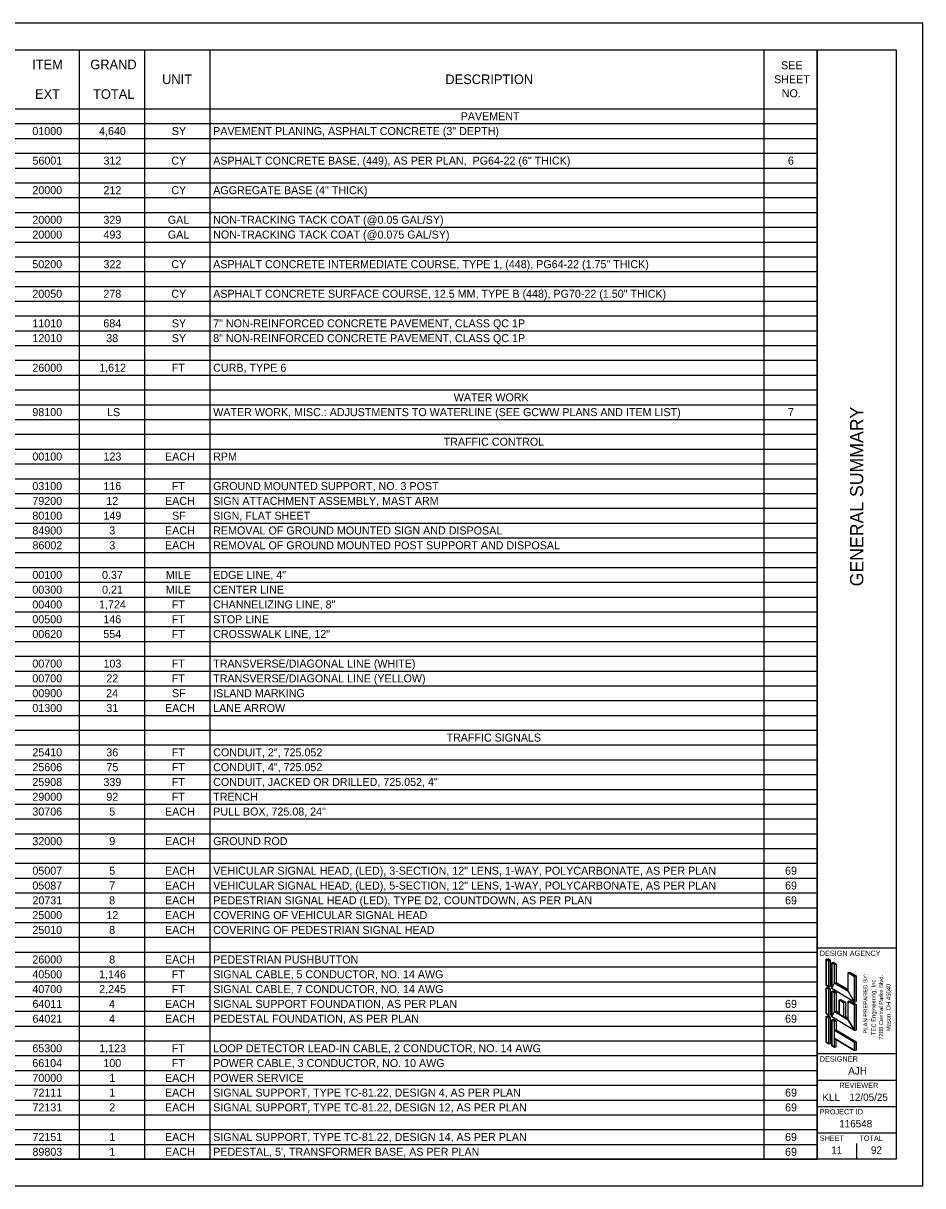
# Model space of a CAD drawing. Extents: x 0 to 34, y 0 to 22.
# Drawn here: x 16.98 to 34, y 0 to 22 of the extents above; entities that cross this region are included whole.
import ezdxf

# ---------------------------------------------------------------- set-up
doc = ezdxf.new("R2010")
doc.units = 0
for name, color, linetype in [('Default', 7, 'Continuous'), ('SH_Border', 7, 'Continuous'), ('SH_Cut_Line', 7, 'Continuous'), ('SH_Data', 7, 'Continuous'), ('SH_Text', 7, 'Continuous')]:
    doc.layers.add(name, color=color, linetype=linetype)

msp = doc.modelspace()

# ---------------------------------------------------------------- linework, layer by layer
at = {"layer": 'SH_Border'}
for p, q in [((32, 0.5), (32, 21.5)), ((32, 4.5), (33.5, 4.5)), ((32, 2.5), (33.5, 2.5)), ((32, 2), (33.5, 2)), ((32, 1.5), (33.5, 1.5)), ((32, 1), (33.5, 1))]:
    msp.add_line(p, q, dxfattribs=at)
msp.add_lwpolyline([(1.5, 21.5), (33.5, 21.5), (33.5, 0.5), (1.5, 0.5)], close=True, dxfattribs=at)
at = {"layer": 'SH_Cut_Line'}
msp.add_lwpolyline([(0, 0), (34, 0), (34, 22), (0, 22)], close=True, dxfattribs=at)
at = {"layer": 'SH_Data'}
for p, q in [((32.75, 3.5), (32.75, 3.5)), ((32.375, 0.675), (32.375, 0.675)), ((32.75, 0.5), (32.75, 0.8))]:
    msp.add_line(p, q, dxfattribs=at)
at = {"layer": 'SH_Text'}
for p, q in [((1.5, 21.5), (32, 21.5)), ((18.035, 21.5), (18.035, 0.502)), ((19.27, 21.5), (19.27, 0.502)), ((20.505, 21.5), (20.505, 0.502)), ((30.995, 21.5), (30.995, 0.502)), ((32, 21.5), (32, 0.502)), ((1.5, 20.38), (32, 20.38)), ((1.5, 20.1), (32, 20.1)), ((1.5, 19.82), (32, 19.82)), ((1.5, 19.54), (32, 19.54)), ((1.5, 19.26), (32, 19.26)), ((1.5, 18.98), (32, 18.98)), ((1.5, 18.7), (32, 18.7)), ((1.5, 18.42), (32, 18.42)), ((1.5, 18.14), (32, 18.14)), ((1.5, 17.86), (32, 17.86)), ((1.5, 17.58), (32, 17.58)), ((1.5, 17.3), (32, 17.3)), ((1.5, 17.021), (32, 17.021)), ((1.5, 16.741), (32, 16.741)), ((1.5, 16.461), (32, 16.461)), ((1.5, 16.181), (32, 16.181)), ((1.5, 15.901), (32, 15.901)), ((1.5, 15.621), (32, 15.621)), ((1.5, 15.341), (32, 15.341)), ((1.5, 15.061), (32, 15.061)), ((1.5, 14.781), (32, 14.781)), ((1.5, 14.501), (32, 14.501)), ((1.5, 14.221), (32, 14.221)), ((1.5, 13.941), (32, 13.941)), ((1.5, 13.661), (32, 13.661)), ((1.5, 13.381), (32, 13.381)), ((1.5, 13.101), (32, 13.101)), ((1.5, 12.821), (32, 12.821)), ((1.5, 12.541), (32, 12.541)), ((1.5, 12.261), (32, 12.261)), ((1.5, 11.981), (32, 11.981)), ((1.5, 11.701), (32, 11.701)), ((1.5, 11.421), (32, 11.421)), ((1.5, 11.141), (32, 11.141)), ((1.5, 10.861), (32, 10.861)), ((1.5, 10.581), (32, 10.581)), ((1.5, 10.301), (32, 10.301)), ((1.5, 10.021), (32, 10.021)), ((1.5, 9.741), (32, 9.741)), ((1.5, 9.461), (32, 9.461)), ((1.5, 9.181), (32, 9.181)), ((1.5, 8.901), (32, 8.901)), ((1.5, 8.621), (32, 8.621)), ((1.5, 8.342), (32, 8.342)), ((1.5, 8.062), (32, 8.062)), ((1.5, 7.782), (32, 7.782)), ((1.5, 7.502), (32, 7.502)), ((1.5, 7.222), (32, 7.222)), ((1.5, 6.942), (32, 6.942)), ((1.5, 6.662), (32, 6.662)), ((1.5, 6.382), (32, 6.382)), ((1.5, 6.102), (32, 6.102)), ((1.5, 5.822), (32, 5.822)), ((1.5, 5.542), (32, 5.542)), ((1.5, 5.262), (32, 5.262)), ((1.5, 4.982), (32, 4.982)), ((1.5, 4.702), (32, 4.702)), ((1.5, 4.422), (32, 4.422)), ((32.169, 4.285), (32.201, 4.294)), ((32.169, 3.799), (32.169, 4.285)), ((32.223, 4.253), (32.169, 4.285)), ((32.255, 4.261), (32.201, 4.294)), ((32.223, 4.253), (32.255, 4.261)), ((32.223, 3.767), (32.223, 4.253)), ((32.255, 3.775), (32.255, 4.261)), ((32.277, 4.221), (32.309, 4.229)), ((32.331, 4.188), (32.277, 4.221)), ((32.277, 3.735), (32.277, 4.221)), ((32.309, 4.229), (32.363, 4.196)), ((32.331, 4.188), (32.363, 4.196)), ((32.331, 3.837), (32.331, 4.188)), ((32.363, 4.196), (32.363, 3.845)), ((1.5, 4.142), (32, 4.142)), ((32.587, 4.034), (32.62, 4.042)), ((32.587, 3.683), (32.587, 4.034)), ((32.709, 3.961), (32.587, 4.034)), ((32.62, 4.042), (32.741, 3.97)), ((32.709, 3.961), (32.741, 3.97)), ((32.709, 3.475), (32.709, 3.961)), ((32.741, 3.97), (32.741, 3.484)), ((1.5, 3.862), (32, 3.862)), ((32.223, 3.767), (32.169, 3.799)), ((32.169, 3.745), (32.201, 3.754)), ((32.169, 3.259), (32.169, 3.745)), ((32.223, 3.713), (32.169, 3.745)), ((32.255, 3.722), (32.201, 3.754)), ((32.223, 3.767), (32.255, 3.775)), ((32.331, 3.837), (32.363, 3.845)), ((32.587, 3.683), (32.331, 3.837)), ((32.363, 3.845), (32.587, 3.711)), ((1.5, 3.582), (32, 3.582)), ((32.223, 3.713), (32.255, 3.722)), ((32.223, 3.227), (32.223, 3.713)), ((32.255, 3.236), (32.255, 3.722)), ((32.709, 3.475), (32.277, 3.735)), ((32.277, 3.681), (32.309, 3.689)), ((32.277, 3.195), (32.277, 3.681)), ((32.331, 3.648), (32.277, 3.681)), ((32.309, 3.689), (32.363, 3.656)), ((32.331, 3.648), (32.363, 3.656)), ((32.331, 3.297), (32.331, 3.648)), ((32.363, 3.656), (32.363, 3.305)), ((32.415, 3.519), (32.448, 3.527)), ((32.448, 3.527), (32.535, 3.474)), ((1.5, 3.302), (32, 3.302)), ((32.331, 3.297), (32.363, 3.305)), ((32.363, 3.305), (32.415, 3.274)), ((32.415, 3.519), (32.415, 3.247)), ((32.415, 3.519), (32.503, 3.466)), ((32.503, 3.466), (32.535, 3.474)), ((32.503, 3.466), (32.503, 3.194)), ((32.535, 3.474), (32.535, 3.202)), ((32.587, 3.494), (32.62, 3.502)), ((32.587, 3.143), (32.587, 3.494)), ((32.709, 3.421), (32.587, 3.494)), ((32.62, 3.502), (32.741, 3.43)), ((32.709, 3.475), (32.741, 3.484)), ((32.709, 3.421), (32.741, 3.43)), ((32.709, 2.935), (32.709, 3.421)), ((32.741, 3.43), (32.741, 2.944)), ((32.223, 3.227), (32.169, 3.259)), ((32.169, 3.205), (32.201, 3.215)), ((32.169, 2.719), (32.169, 3.205)), ((32.223, 3.173), (32.169, 3.205)), ((32.255, 3.181), (32.201, 3.215)), ((32.222, 3.173), (32.255, 3.181)), ((32.223, 3.227), (32.255, 3.236)), ((32.223, 2.687), (32.223, 3.173)), ((32.255, 2.695), (32.255, 3.181)), ((32.709, 2.935), (32.277, 3.195)), ((32.277, 3.141), (32.309, 3.151)), ((32.331, 3.108), (32.277, 3.141)), ((32.277, 2.655), (32.277, 3.141)), ((32.309, 3.151), (32.363, 3.116)), ((32.415, 3.247), (32.331, 3.297)), ((32.331, 3.108), (32.363, 3.116)), ((32.331, 2.944), (32.331, 3.108)), ((32.363, 3.116), (32.363, 2.952)), ((32.503, 3.194), (32.535, 3.202)), ((32.587, 3.143), (32.503, 3.194)), ((32.535, 3.202), (32.587, 3.171)), ((1.5, 3.022), (32, 3.022)), ((32.331, 2.944), (32.363, 2.952)), ((32.331, 2.944), (32.709, 2.717)), ((32.363, 2.952), (32.741, 2.725)), ((32.709, 2.935), (32.741, 2.944)), ((1.5, 2.742), (32, 2.742)), ((32.223, 2.687), (32.169, 2.719)), ((32.223, 2.687), (32.255, 2.695)), ((32.331, 2.622), (32.277, 2.655)), ((32.331, 2.787), (32.709, 2.56)), ((32.331, 2.622), (32.331, 2.787)), ((32.363, 2.63), (32.363, 2.767)), ((32.709, 2.717), (32.741, 2.725)), ((32.709, 2.56), (32.709, 2.717)), ((32.741, 2.725), (32.741, 2.568)), ((1.5, 2.462), (32, 2.462)), ((32.331, 2.622), (32.363, 2.63)), ((32.709, 2.56), (32.741, 2.568)), ((1.5, 2.182), (32, 2.182)), ((1.5, 1.902), (32, 1.902)), ((1.5, 1.622), (32, 1.622)), ((1.5, 1.342), (32, 1.342)), ((1.5, 1.062), (32, 1.062)), ((1.5, 0.782), (32, 0.782)), ((1.5, 0.502), (32, 0.502))]:
    msp.add_line(p, q, dxfattribs=at)
for points in [[(32.169, 3.799), (32.223, 3.767), (32.223, 4.253), (32.169, 4.285)], [(32.277, 3.735), (32.331, 3.837), (32.331, 4.188), (32.277, 4.221)], [(32.709, 3.475), (32.587, 3.683), (32.587, 4.034), (32.709, 3.961)], [(32.169, 3.259), (32.223, 3.227), (32.223, 3.713), (32.169, 3.745)], [(32.277, 3.735), (32.331, 3.837), (32.587, 3.683), (32.709, 3.475)], [(32.277, 3.195), (32.331, 3.297), (32.331, 3.648), (32.277, 3.681)], [(32.415, 3.247), (32.415, 3.519), (32.503, 3.466), (32.503, 3.194)], [(32.709, 2.935), (32.587, 3.143), (32.587, 3.494), (32.709, 3.421)], [(32.169, 2.719), (32.223, 2.687), (32.223, 3.173), (32.169, 3.205)], [(32.277, 3.195), (32.331, 3.297), (32.587, 3.143), (32.709, 2.935)], [(32.277, 2.655), (32.331, 2.622), (32.331, 3.108), (32.277, 3.141)], [(32.331, 2.787), (32.331, 2.944), (32.709, 2.717), (32.709, 2.56)]]:
    msp.add_lwpolyline(points, close=True, dxfattribs=at)

# ---------------------------------------------------------------- texts
at = {"layer": 'Default'}
for s, p in [('PLAN PREPARED BY:', (32.954, 2.88)), ('TEC Engineering, Inc.', (33.11, 2.851)), ('7288 Central Parke Blvd.', (33.25, 2.762)), ('Mason, OH 45040', (33.39, 2.925))]:
    msp.add_text(s, height=0.08, rotation=90, dxfattribs=at).set_placement(p)
at = {"layer": 'SH_Data'}
msp.add_text('GENERAL SUMMARY', height=0.25, rotation=90, dxfattribs=at).set_placement((32.875, 11.344))
for s, height, p in [('DESIGN AGENCY', 0.1, (32.05, 4.35)), ('DESIGNER', 0.1, (32.05, 2.35)), ('AJH', 0.14, (32.59, 2.105)), ('REVIEWER', 0.1, (32.422, 1.85)), ('KLL', 0.14, (32.101, 1.605)), ('12/05/25', 0.14, (32.611, 1.605)), ('PROJECT ID', 0.1, (32.05, 1.35)), ('116548', 0.14, (32.419, 1.105)), ('SHEET', 0.1, (32.05, 0.85)), ('TOTAL', 0.1, (32.8, 0.85)), ('11', 0.14, (32.269, 0.605)), ('92', 0.14, (33.019, 0.605))]:
    msp.add_text(s, height=height, dxfattribs=at).set_placement(p)
at = {"layer": 'SH_Text'}
for s, height, p in [('ITEM', 0.1818, (17.145, 21.129)), ('GRAND', 0.1818, (18.245, 21.129)), ('SEE ', 0.1515, (31.32, 21.129)), ('UNIT', 0.1818, (19.604, 20.849)), ('DESCRIPTION', 0.18181, (24.965, 20.849)), ('SHEET ', 0.1515, (31.187, 20.864)), ('EXT', 0.1818, (17.199, 20.569)), ('TOTAL', 0.1818, (18.297, 20.569)), ('NO.', 0.1515, (31.331, 20.599)), ('PAVEMENT', 0.1515, (25.255, 20.164)), ('01000', 0.1515, (17.149, 19.884)), ('4,640', 0.1515, (18.411, 19.884)), ('SY', 0.1515, (19.788, 19.884)), ('PAVEMENT PLANING, ASPHALT CONCRETE (3" DEPTH)', 0.15151, (20.571, 19.884)), ('56001', 0.1515, (17.151, 19.324)), ('312', 0.1515, (18.495, 19.324)), ('CY', 0.1515, (19.779, 19.324)), ('ASPHALT CONCRETE BASE, (449), AS PER PLAN,  PG64-22 (6" THICK)', 0.15151, (20.571, 19.324)), ('6', 0.152, (31.448, 19.324)), ('AGGREGATE BASE (4" THICK)', 0.15151, (20.571, 18.765)), ('20000', 0.1515, (17.149, 18.765)), ('212', 0.1515, (18.495, 18.765)), ('CY', 0.1515, (19.779, 18.765)), ('20000', 0.1515, (17.149, 18.205)), ('329', 0.1515, (18.494, 18.205)), ('GAL', 0.1515, (19.713, 18.205)), ('NON-TRACKING TACK COAT (@0.05 GAL/SY)', 0.15151, (20.571, 18.205)), ('20000', 0.1515, (17.149, 17.925)), ('493', 0.1515, (18.495, 17.925)), ('GAL', 0.1515, (19.713, 17.925)), ('NON-TRACKING TACK COAT (@0.075 GAL/SY)', 0.15151, (20.571, 17.925)), ('50200', 0.1515, (17.149, 17.365)), ('322', 0.1515, (18.495, 17.365)), ('CY', 0.1515, (19.779, 17.365)), ('ASPHALT CONCRETE INTERMEDIATE COURSE, TYPE 1, (448), PG64-22 (1.75" THICK)', 0.15151, (20.571, 17.365)), ('20050', 0.1515, (17.149, 16.805)), ('278', 0.1515, (18.493, 16.805)), ('CY', 0.1515, (19.779, 16.805)), ('ASPHALT CONCRETE SURFACE COURSE, 12.5 MM, TYPE B (448), PG70-22 (1.50" THICK)', 0.15151, (20.571, 16.805)), ('11010', 0.1515, (17.149, 16.245)), ('684', 0.1515, (18.492, 16.245)), ('SY', 0.1515, (19.788, 16.245)), ('7" NON-REINFORCED CONCRETE PAVEMENT, CLASS QC 1P', 0.15151, (20.571, 16.245)), ('12010', 0.1515, (17.149, 15.965)), ('38', 0.1515, (18.548, 15.965)), ('SY', 0.1515, (19.788, 15.965)), ('8" NON-REINFORCED CONCRETE PAVEMENT, CLASS QC 1P', 0.15151, (20.571, 15.965)), ('26000', 0.1515, (17.149, 15.405)), ('1,612', 0.1515, (18.414, 15.405)), ('FT', 0.1515, (19.786, 15.405)), ('CURB, TYPE 6', 0.15151, (20.571, 15.405)), ('WATER WORK', 0.1515, (25.124, 14.845)), ('98100', 0.1515, (17.149, 14.565)), ('LS', 0.1515, (18.562, 14.565)), ('WATER WORK, MISC.: ADJUSTMENTS TO WATERLINE (SEE GCWW PLANS AND ITEM LIST)', 0.15151, (20.571, 14.565)), ('7', 0.152, (31.448, 14.565)), ('TRAFFIC CONTROL', 0.15151, (24.933, 14.005)), ('00100', 0.1515, (17.149, 13.725)), ('123', 0.1515, (18.495, 13.725)), ('EACH', 0.1515, (19.659, 13.725)), ('RPM', 0.1515, (20.571, 13.725)), ('03100', 0.1515, (17.149, 13.165)), ('116', 0.1515, (18.493, 13.165)), ('FT', 0.1515, (19.786, 13.165)), ('GROUND MOUNTED SUPPORT, NO. 3 POST', 0.15151, (20.571, 13.165)), ('79200', 0.1515, (17.149, 12.885)), ('12', 0.1515, (18.549, 12.885)), ('EACH', 0.1515, (19.659, 12.885)), ('SIGN ATTACHMENT ASSEMBLY, MAST ARM', 0.15151, (20.571, 12.885)), ('80100', 0.1515, (17.149, 12.605)), ('149', 0.1515, (18.494, 12.605)), ('SF', 0.1515, (19.793, 12.605)), ('SIGN, FLAT SHEET', 0.15151, (20.571, 12.605)), ('84900', 0.1515, (17.149, 12.325)), ('3', 0.152, (18.604, 12.325)), ('EACH', 0.1515, (19.659, 12.325)), ('REMOVAL OF GROUND MOUNTED SIGN AND DISPOSAL', 0.15151, (20.571, 12.325)), ('86002', 0.1515, (17.151, 12.045)), ('3', 0.152, (18.604, 12.045)), ('EACH', 0.1515, (19.659, 12.045)), ('REMOVAL OF GROUND MOUNTED POST SUPPORT AND DISPOSAL', 0.15151, (20.571, 12.045)), ('00100', 0.1515, (17.149, 11.485)), ('0.37', 0.1515, (18.467, 11.485)), ('MILE', 0.1515, (19.676, 11.485)), ('EDGE LINE, 4"', 0.15151, (20.571, 11.485)), ('00300', 0.1515, (17.149, 11.205)), ('0.21', 0.1515, (18.468, 11.205)), ('MILE', 0.1515, (19.676, 11.205)), ('CENTER LINE', 0.15151, (20.571, 11.205)), ('00400', 0.1515, (17.149, 10.925)), ('1,724', 0.1515, (18.411, 10.925)), ('FT', 0.1515, (19.786, 10.925)), ('CHANNELIZING LINE, 8"', 0.15151, (20.571, 10.925)), ('00500', 0.1515, (17.149, 10.645)), ('146', 0.1515, (18.493, 10.645)), ('FT', 0.1515, (19.786, 10.645)), ('STOP LINE', 0.1515, (20.571, 10.645)), ('00620', 0.1515, (17.149, 10.366)), ('554', 0.1515, (18.492, 10.366)), ('FT', 0.1515, (19.786, 10.366)), ('CROSSWALK LINE, 12"', 0.15151, (20.571, 10.366)), ('00700', 0.1515, (17.149, 9.806)), ('103', 0.1515, (18.495, 9.806)), ('FT', 0.1515, (19.786, 9.806)), ('TRANSVERSE/DIAGONAL LINE (WHITE)', 0.15151, (20.571, 9.806)), ('TRANSVERSE/DIAGONAL LINE (YELLOW)', 0.15151, (20.571, 9.526)), ('00700', 0.1515, (17.149, 9.526)), ('22', 0.1515, (18.549, 9.526)), ('FT', 0.1515, (19.786, 9.526)), ('00900', 0.1515, (17.149, 9.246)), ('24', 0.1515, (18.546, 9.246)), ('SF', 0.1515, (19.793, 9.246)), ('ISLAND MARKING', 0.15151, (20.571, 9.246)), ('01300', 0.1515, (17.149, 8.966)), ('31', 0.1515, (18.549, 8.966)), ('EACH', 0.1515, (19.659, 8.966)), ('LANE ARROW', 0.1515, (20.571, 8.966)), ('TRAFFIC SIGNALS', 0.15151, (24.986, 8.406)), ('25410', 0.1515, (17.149, 8.126)), ('36', 0.1515, (18.548, 8.126)), ('FT', 0.1515, (19.786, 8.126)), ('CONDUIT, 2", 725.052', 0.15151, (20.571, 8.126)), ('25606', 0.1515, (17.149, 7.846)), ('75', 0.1515, (18.55, 7.846)), ('FT', 0.1515, (19.786, 7.846)), ('CONDUIT, 4", 725.052', 0.15151, (20.571, 7.846)), ('25908', 0.1515, (17.149, 7.566)), ('339', 0.1515, (18.494, 7.566)), ('FT', 0.1515, (19.786, 7.566)), ('CONDUIT, JACKED OR DRILLED, 725.052, 4"', 0.15151, (20.571, 7.566)), ('29000', 0.1515, (17.149, 7.286)), ('92', 0.1515, (18.549, 7.286)), ('FT', 0.1515, (19.786, 7.286)), ('TRENCH', 0.1515, (20.571, 7.286)), ('30706', 0.1515, (17.149, 7.006)), ('5', 0.152, (18.604, 7.006)), ('EACH', 0.1515, (19.659, 7.006)), ('PULL BOX, 725.08, 24"', 0.15151, (20.571, 7.006)), ('32000', 0.1515, (17.149, 6.446)), ('9', 0.152, (18.603, 6.446)), ('EACH', 0.1515, (19.659, 6.446)), ('GROUND ROD', 0.1515, (20.571, 6.446)), ('05007', 0.1515, (17.15, 5.886)), ('5', 0.152, (18.604, 5.886)), ('EACH', 0.1515, (19.659, 5.886)), ('VEHICULAR SIGNAL HEAD, (LED), 3-SECTION, 12" LENS, 1-WAY, POLYCARBONATE, AS PER PLAN', 0.15151, (20.571, 5.886)), ('69', 0.1515, (31.394, 5.886)), ('05087', 0.1515, (17.15, 5.606)), ('7', 0.152, (18.603, 5.606)), ('EACH', 0.1515, (19.659, 5.606)), ('VEHICULAR SIGNAL HEAD, (LED), 5-SECTION, 12" LENS, 1-WAY, POLYCARBONATE, AS PER PLAN', 0.15151, (20.571, 5.606)), ('69', 0.1515, (31.394, 5.606)), ('20731', 0.1515, (17.151, 5.326)), ('8', 0.152, (18.602, 5.326)), ('EACH', 0.1515, (19.659, 5.326)), ('PEDESTRIAN SIGNAL HEAD (LED), TYPE D2, COUNTDOWN, AS PER PLAN', 0.15151, (20.571, 5.326)), ('69', 0.1515, (31.394, 5.326)), ('25000', 0.1515, (17.149, 5.046)), ('12', 0.1515, (18.549, 5.046)), ('EACH', 0.1515, (19.659, 5.046)), ('COVERING OF VEHICULAR SIGNAL HEAD', 0.15151, (20.571, 5.046)), ('25010', 0.1515, (17.149, 4.766)), ('8', 0.152, (18.602, 4.766)), ('EACH', 0.1515, (19.659, 4.766)), ('COVERING OF PEDESTRIAN SIGNAL HEAD', 0.15151, (20.571, 4.766)), ('26000', 0.1515, (17.149, 4.206)), ('8', 0.152, (18.602, 4.206)), ('EACH', 0.1515, (19.659, 4.206)), ('PEDESTRIAN PUSHBUTTON', 0.15151, (20.571, 4.206)), ('40500', 0.1515, (17.149, 3.926)), ('1,146', 0.1515, (18.412, 3.926)), ('FT', 0.1515, (19.786, 3.926)), ('SIGNAL CABLE, 5 CONDUCTOR, NO. 14 AWG', 0.15151, (20.571, 3.926)), ('40700', 0.1515, (17.149, 3.646)), ('2,245', 0.1515, (18.414, 3.646)), ('FT', 0.1515, (19.786, 3.646)), ('SIGNAL CABLE, 7 CONDUCTOR, NO. 14 AWG', 0.15151, (20.571, 3.646)), ('64011', 0.1515, (17.151, 3.366)), ('EACH', 0.1515, (19.659, 3.366)), ('SIGNAL SUPPORT FOUNDATION, AS PER PLAN', 0.15151, (20.571, 3.366)), ('69', 0.1515, (31.394, 3.366)), ('4', 0.152, (18.601, 3.366)), ('64021', 0.1515, (17.151, 3.086)), ('4', 0.152, (18.601, 3.086)), ('EACH', 0.1515, (19.659, 3.086)), ('PEDESTAL FOUNDATION, AS PER PLAN', 0.15151, (20.571, 3.086)), ('69', 0.1515, (31.394, 3.086)), ('65300', 0.1515, (17.149, 2.526)), ('1,123', 0.1515, (18.414, 2.526)), ('FT', 0.1515, (19.786, 2.526)), ('LOOP DETECTOR LEAD-IN CABLE, 2 CONDUCTOR, NO. 14 AWG', 0.15151, (20.571, 2.526)), ('66104', 0.1515, (17.148, 2.246)), ('100', 0.1515, (18.493, 2.246)), ('FT', 0.1515, (19.786, 2.246)), ('POWER CABLE, 3 CONDUCTOR, NO. 10 AWG', 0.15151, (20.571, 2.246)), ('70000', 0.1515, (17.149, 1.966)), ('1', 0.152, (18.604, 1.966)), ('EACH', 0.1515, (19.659, 1.966)), ('POWER SERVICE', 0.15151, (20.571, 1.966)), ('72111', 0.1515, (17.151, 1.687)), ('1', 0.152, (18.604, 1.687)), ('EACH', 0.1515, (19.659, 1.687)), ('SIGNAL SUPPORT, TYPE TC-81.22, DESIGN 4, AS PER PLAN', 0.15151, (20.571, 1.687)), ('69', 0.1515, (31.394, 1.687)), ('72131', 0.1515, (17.151, 1.407)), ('2', 0.152, (18.604, 1.407)), ('EACH', 0.1515, (19.659, 1.407)), ('SIGNAL SUPPORT, TYPE TC-81.22, DESIGN 12, AS PER PLAN', 0.15151, (20.571, 1.407)), ('69', 0.1515, (31.394, 1.407)), ('72151', 0.1515, (17.151, 0.847)), ('1', 0.152, (18.604, 0.847)), ('EACH', 0.1515, (19.659, 0.847)), ('SIGNAL SUPPORT, TYPE TC-81.22, DESIGN 14, AS PER PLAN', 0.15151, (20.571, 0.847)), ('69', 0.1515, (31.394, 0.847)), ('89803', 0.1515, (17.151, 0.567)), ('1', 0.152, (18.604, 0.567)), ('EACH', 0.1515, (19.659, 0.567)), ("PEDESTAL, 5', TRANSFORMER BASE, AS PER PLAN", 0.15151, (20.571, 0.567)), ('69', 0.1515, (31.394, 0.567))]:
    msp.add_text(s, height=height, dxfattribs=at).set_placement(p)

doc.saveas('drawing.dxf')
